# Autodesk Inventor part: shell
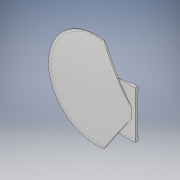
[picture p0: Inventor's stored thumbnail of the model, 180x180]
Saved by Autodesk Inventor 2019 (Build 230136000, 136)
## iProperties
Created: 2021-03
Part Number: shell
Material: 一般
Document SubType Name: Modeling
Designer: kikut
Density: 1 g/cm^3
Appearance: 既定
Author: kikut
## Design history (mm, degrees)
sketch "スケッチ2"
  geometry: L1 (-300, 0)-(300, 0); A1 r 300 centre (0, 0) between (300, 0) and (-300, 0); 1 further point
  constraints: 2 end point, 2 point on circle, 1 centre point, 1 coincident, 1 horizontal
  dimensions: "d1" = 300 radius of A1
revolve "回転1" sketch "スケッチ2" stored, may be unused: angle "d2" = 180 deg
sketch "スケッチ3"
  geometry: L1 (500, 288)-(-500, 288); L2 (-500, 288)-(-500, -512); L3 (-500, -512)-(500, -512); L4 (500, -512)-(500, 288); L5 (0, -580)-(0, 540) reference; 1 further point
  constraints: 8 end point, 2 parallel, 1 horizontal, 1 perpendicular, 1 other
  dimensions: "d3" = 288 distance from line of L1 point (0, 0); "d4" = 800 distance of L1.end L2.end; "d5" = 1000 distance of L2.end L3.end
extrude "押し出し1" cut sketch "スケッチ3" stored distance "d7" = 800; taper "d8" = 0 deg
sketch "スケッチ6"
  geometry: C1 r 80 at (0, 0); C2 r 200 at (0, 0); 1 further point
  constraints: 2 centre point, 2 coincident
  dimensions: "d9" = 160 diameter of C1; "d10" = 400 diameter of C2
extrude "押し出し2" cut sketch "スケッチ6" distance "d11" = 100; taper "d12" = 0 deg
sketch "スケッチ7"
  geometry: L1 (-13.892, 78.785)-(-70, 0); L2 (-70, 0)-(-13.892, -78.785); C1 r 120 at (0, 0); A1 r 80 centre (0, 0) between (-13.892, -78.785) and (-13.892, 78.785) reference; A2 r 80 centre (0, 0) between (-13.892, -78.785) and (-13.892, 78.785); 1 further point
  constraints: 4 end point, 4 point on circle, 2 centre point, 2 coincident
  dimensions: "d13" = 0 horizontal distance of L2.end L1.start; "d14" = 160 deg dimension on point (0, 0) L2.end L1.start; "d15" = 70 distance of point (0, 0) L1.end; "d16" = 240 diameter of C1
extrude "押し出し3" cut sketch "スケッチ7" distance "d17" = 100; taper "d18" = 0 deg
sketch "スケッチ8"
  geometry: L1 (-30, -40)-(-70, -40); L2 (-70, -40)-(-70, 40); L3 (-70, 40)-(-30, 40); L4 (-30, 40)-(-30, -40); L5 (110, 0)-(-100, 0) reference; 1 further point
  constraints: 8 end point, 2 parallel, 1 horizontal, 1 perpendicular, 1 other
  dimensions: "d19" = 80 distance of L1.end L2.end; "d20" = 70 distance from line of point (0, 0) L2; "d21" = 40 distance of L1.start L1.end
extrude "押し出し4" join sketch "スケッチ8" distance "d22" = 5; taper "d23" = 0 deg
sketch "スケッチ9"
  geometry: L1 (0, 298)-(0, -298); A1 r 298 centre (0, 0) between (0, 298) and (0, -298); 1 further point
  constraints: 2 end point, 2 point on circle, 1 centre point, 1 coincident, 1 vertical
  dimensions: "d24" = 298 radius of A1
revolve "回転2" sketch "スケッチ9" stored, may be unused: angle "d25" = 90 deg
node "ソリッド1"
